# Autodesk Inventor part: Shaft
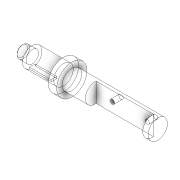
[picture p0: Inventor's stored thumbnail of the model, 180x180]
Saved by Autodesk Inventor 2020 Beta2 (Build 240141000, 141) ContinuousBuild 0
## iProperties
Created: 2019-03
Part Number: Shaft
Material: Generic
Document SubType Name: Modeling
Designer: LENOVO-CADCIM
Density: 1 g/cm^3
Appearance: Default
Author: LENOVO-CADCIM
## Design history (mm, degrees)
sketch "Sketch1"
  geometry: L1 (284.311, 0)-(1023.188, 0); L2 (391.676, 0)-(391.676, -18); L3 (391.676, -18)-(420.576, -18); L4 (420.576, -18)-(420.576, -28); L5 (420.576, -28)-(510.376, -28); L6 (510.376, -28)-(510.376, -43.6); L7 (510.376, -43.6)-(534.376, -43.6); L8 (534.376, -43.6)-(534.376, -28); L9 (534.376, -28)-(781.476, -28); L10 (781.476, -28)-(781.476, 0); L11 (391.676, 0)-(781.476, 0); 1 further point
  constraints: 22 end point, 8 perpendicular, 5 point on line, 1 collinear, 1 horizontal
  dimensions: "d0" = 28.9 distance of L2.end L3.end; "d1" = 89.8 distance of L4.end L5.end; "d2" = 24 distance of L6.end L7.end; "d3" = 247.1 distance of L8.end L9.end; "d4" = 56 diameter of L9 L1; "d5" = 87.2 diameter of L7 L1; "d6" = 36 diameter of L3 L1
revolve "Revolution1" sketch "Sketch1" stored, may be unused: angle "d7" = 90 deg
sketch "Sketch4"
  geometry: L1 (-781.476, 28)-(-534.376, 28) reference; L2 (-601, 28)-(-766.376, 28); L3 (-766.376, 28)-(-766.376, -3.1); L4 (-766.376, -3.1)-(-601, -3.1); L5 (-601, -3.1)-(-601, 28); L6 (-781.476, -28)-(-534.376, -28) reference; 2 further points
  constraints: 8 end point, 2 parallel, 1 horizontal, 1 perpendicular, 1 point on line
  dimensions: "d16" = 24.9 distance between parallel lines of L6 L4; "d17" = 15.1 distance from line of L1.start L3
extrude "Extrusion3" cut sketch "Sketch4" stored distance "d18" = 257; taper "d19" = 0 deg
sketch "Sketch6"
  geometry: L1 (-209.324, 45.828)-(-209.324, 9.828) reference; L2 (-209.324, 27.828)-(292.122, 27.828); L3 (0, 55.828)-(0, -0.172) reference; 5 further points
  constraints: 2 end point, 2 point on line, 1 horizontal, 1 midpoint
  dimensions: "d24" = 100 distance of point (46.9, 27.828) point (146.9, 27.828); "d25" = 46.9 distance from line of L3 point (46.9, 27.828)
hole "Hole1" sketch "Sketch6" at (46.9, 27.828), (146.9, 27.828) diameter "d26" = 12.5; stored, may be unused: countersink angle "d30" = 90 deg, drill point angle "d32" = 118 deg; dims "d27" = 6, "d28" = 100, "d29" = 25, "d31" = 310
chamfer "Chamfer1" distance "d33" = 3; stored, may be unused: second distance "d34" = 2, angle "d35" = 45 deg
sketch "Sketch7"
  geometry: L1 (8, -22)-(-8, -22); L2 (-8, -22)-(-8, -26.833); L3 (8, -26.833)-(8, -22); L4 (0, 0)-(0, 64); C1 r 28 at (0, 0) reference; A1 r 28 centre (0, 0) between (-8, -26.833) and (8, -26.833); A2 r 28 centre (0, 0) between (8, -26.833) and (-8, -26.833) reference; 4 further points
  constraints: 8 end point, 3 point on circle, 1 centre point, 1 coincident, 1 concentric, 1 horizontal, 1 parallel, 1 perpendicular, 1 vertical, 1 other
  dimensions: "d36" = 16 distance between parallel lines of L3 L2; "d37" = 50 distance from line of point (0, 28) L1
extrude "Extrusion5" cut sketch "Sketch7" distance "d38" = 62.5; taper "d39" = 0 deg
body "Solid1"
